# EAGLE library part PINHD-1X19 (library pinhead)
PIN HEADER
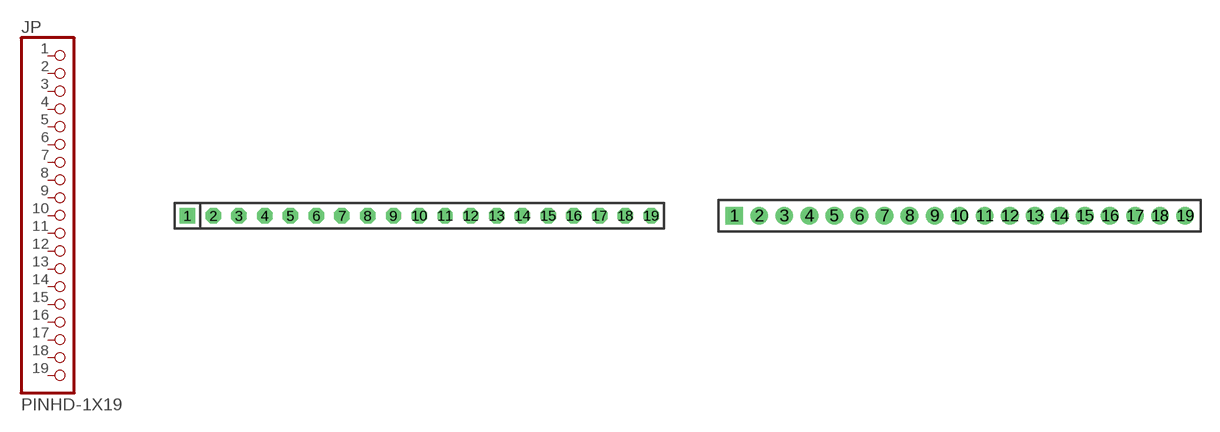
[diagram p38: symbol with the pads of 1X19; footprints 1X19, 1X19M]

Designator prefix JP

## PINHD-1X19  [1X19]
1  1  pas
2  2  pas
3  3  pas
4  4  pas
5  5  pas
6  6  pas
7  7  pas
8  8  pas
9  9  pas
10  10  pas
11  11  pas
12  12  pas
13  13  pas
14  14  pas
15  15  pas
16  16  pas
17  17  pas
18  18  pas
19  19  pas

## PINHD-1X19M  [1X19M]
Pads as for 1X19

## Footprint 1X19 (pad centres in mm)
PIN HEADER - 0.1"
drill 1.016 square: 1 -22.86,0
drill 1.016 octagon: 2 -20.32,0; 3 -17.78,0; 4 -15.24,0; 5 -12.7,0; 6 -10.16,0; 7 -7.62,0; 8 -5.08,0; 9 -2.54,0; 10 0,0; 11 2.54,0; 12 5.08,0; 13 7.62,0; 14 10.16,0; 15 12.7,0; 16 15.24,0; 17 17.78,0; 18 20.32,0; 19 22.86,0

## Footprint 1X19M (pad centres in mm)
PIN HEADER - 2MM"
drill 0.914 square: 1 -18,0
drill 0.914 round: 2 -16,0; 3 -14,0; 4 -12,0; 5 -10,0; 6 -8,0; 7 -6,0; 8 -4,0; 9 -2,0; 10 0,0; 11 2,0; 12 4,0; 13 6,0; 14 8,0; 15 10,0; 16 12,0; 17 14,0; 18 16,0; 19 18,0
